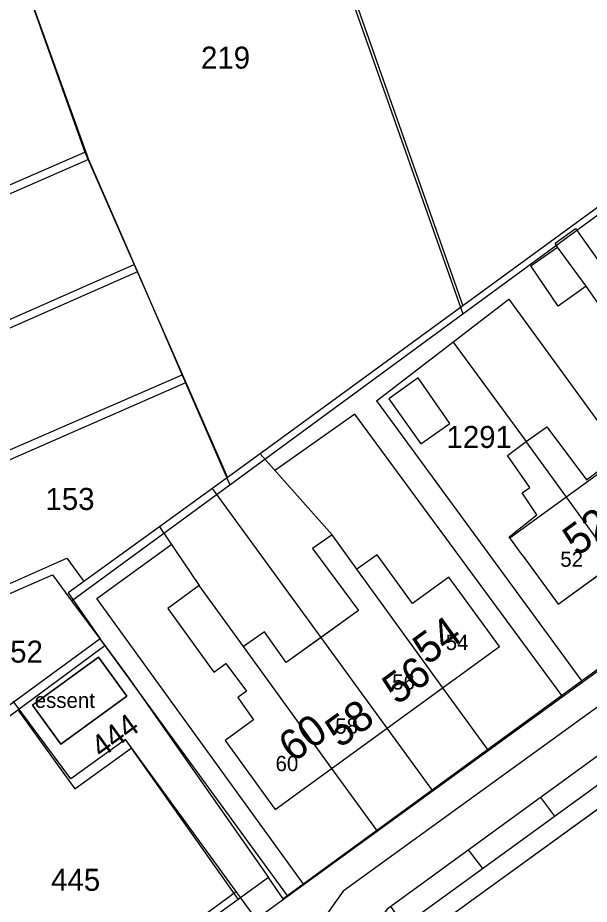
# Model space of a CAD drawing. Extents: x 148816 to 151297, y 399515 to 402500.
# Drawn here: x 149560.2 to 149607, y 400379.3 to 400451.8 of the extents above; entities that cross this region are included whole.
import ezdxf

# ---------------------------------------------------------------- set-up
doc = ezdxf.new("R2010")
doc.units = 0
for name, color, linetype in [('B01 Hoofdgebouw  [D] Norm', 7, 'Continuous'), ('B01 Hoofdgebouw  [T] Norm', 7, 'Continuous'), ('B01 hoofgebouw', 7, 'Continuous'), ('B07 Tussenmuur  [D] Norm', 7, 'Continuous'), ('G01 perceelsgrens', 7, 'Continuous'), ('T04 Haag heg  [D] Gem', 7, 'Continuous'), ('V00 Kant verharding algemeen  [T] Norm', 7, 'Continuous'), ('V00 Kant verharding algemeen secundair  [T] Gem', 7, 'Continuous'), ('Z01 perceelnummer', 7, 'Continuous'), ('Z02 huisnummer', 7, 'Continuous'), ('Z02 Huisnummer  [Tekst] Norm', 7, 'Continuous'), ('Z19 Overige Tekst  [Tekst] Gem', 7, 'Continuous')]:
    doc.layers.add(name, color=color, linetype=linetype)

msp = doc.modelspace()

# ---------------------------------------------------------------- linework, layer by layer
at = {"layer": 'B01 Hoofdgebouw  [D] Norm'}
for p, q in [((149578.674, 400400.387), (149575.05, 400405.38)), ((149580.38, 400401.594), (149578.674, 400400.387))]:
    msp.add_line(p, q, dxfattribs=at)
for points in [[(149610.97, 400423.826), (149606.716, 400429.876), (149604.419, 400428.237), (149602.204, 400431.555), (149604.374, 400433.068), (149604.198, 400433.399), (149605.857, 400434.609), (149614.619, 400422.278)], [(149606.716, 400429.876), (149604.374, 400433.068)], [(149600.411, 400409.373), (149602.683, 400411.165), (149601.475, 400412.977), (149602.113, 400413.406), (149600.275, 400416.035), (149601.807, 400417.17), (149603.491, 400418.38), (149606.741, 400414.039), (149609.549, 400416.132)], [(149595.489, 400406.057), (149592.499, 400403.905), (149589.603, 400407.888), (149587.944, 400406.729), (149585.93, 400409.537), (149584.322, 400408.403), (149588.075, 400403.347), (149585.037, 400401.129), (149582.153, 400399.087), (149580.38, 400401.594)], [(149601.48, 400407.9), (149600.411, 400409.373)], [(149596.68, 400404.42), (149595.489, 400406.057)]]:
    msp.add_lwpolyline(points, dxfattribs=at)
msp.add_lwpolyline([(149590.574, 400420.669), (149593.193, 400416.967), (149595.566, 400418.631), (149592.974, 400422.383)], close=True, dxfattribs=at)
at = {"layer": 'B01 Hoofdgebouw  [T] Norm'}
for p, q in [((149604.42, 400403.85), (149632.08, 400423.92)), ((149601.48, 400407.9), (149604.42, 400403.85)), ((149575.05, 400405.38), (149572.46, 400403.5)), ((149599.62, 400400.38), (149596.68, 400404.42)), ((149572.46, 400403.5), (149576.25, 400398.3)), ((149581.26, 400387.05), (149599.62, 400400.38)), ((149566.8, 400399.51), (149561.39, 400395.6)), ((149569.11, 400396.32), (149566.8, 400399.51)), ((149576.25, 400398.3), (149577.21, 400399.01)), ((149577.21, 400399.01), (149578.9, 400396.73)), ((149578.9, 400396.73), (149578.19, 400396.22)), ((149563.7, 400392.41), (149569.11, 400396.32)), ((149578.19, 400396.22), (149579.48, 400394.39)), ((149561.39, 400395.6), (149563.7, 400392.41)), ((149579.48, 400394.39), (149577.16, 400392.7)), ((149577.16, 400392.7), (149581.26, 400387.05))]:
    msp.add_line(p, q, dxfattribs=at)
at = {"layer": 'B01 hoofgebouw'}
for points in [[(149601.48, 400407.9), (149600.475, 400409.284), (149628.135, 400429.354), (149629.14, 400427.97)], [(149601.48, 400407.9), (149604.42, 400403.85), (149632.08, 400423.92), (149629.14, 400427.97)], [(149596.68, 400404.42), (149595.489, 400406.057), (149592.499, 400403.905), (149589.603, 400407.888), (149587.944, 400406.729), (149585.93, 400409.537), (149584.322, 400408.403), (149588.075, 400403.347), (149582.153, 400399.087), (149580.38, 400401.594), (149578.674, 400400.387), (149575.05, 400405.38)], [(149575.05, 400405.38), (149572.46, 400403.5), (149576.25, 400398.3), (149577.21, 400399.01), (149578.9, 400396.73), (149578.19, 400396.22), (149579.48, 400394.39), (149577.16, 400392.7), (149581.26, 400387.05), (149599.62, 400400.38), (149596.68, 400404.42)], [(149566.8, 400399.51), (149569.11, 400396.32), (149563.7, 400392.41), (149561.39, 400395.6), (149566.8, 400399.51)]]:
    msp.add_lwpolyline(points, dxfattribs=at)
at = {"layer": 'B07 Tussenmuur  [D] Norm'}
for p, q in [((149609.04, 400407.202), (149601.807, 400417.17)), ((149609.04, 400407.202), (149601.807, 400417.17)), ((149594.993, 400397.02), (149587.944, 400406.729)), ((149594.993, 400397.02), (149587.944, 400406.729)), ((149590.427, 400393.705), (149585.037, 400401.129)), ((149590.427, 400393.705), (149585.037, 400401.129)), ((149585.907, 400390.424), (149578.674, 400400.387)), ((149585.907, 400390.424), (149578.674, 400400.387))]:
    msp.add_line(p, q, dxfattribs=at)
at = {"layer": 'G01 perceelsgrens'}
for points in [[(149575.934, 400486.311), (149586.263, 400456.978), (149596.625, 400427.624)], [(149552.339, 400477.996), (149565.983, 400440.231)], [(149596.625, 400427.624), (149607.367, 400435.504), (149617.476, 400442.841)], [(149565.983, 400440.231), (149552.846, 400434.522)], [(149565.983, 400440.231), (149569.974, 400431.04)], [(149569.974, 400431.04), (149546.568, 400420.73), (149523.662, 400410.757)], [(149569.974, 400431.04), (149573.916, 400421.964)], [(149577.538, 400413.624), (149596.625, 400427.624)], [(149573.916, 400421.964), (149548.666, 400410.933), (149527.649, 400401.679)], [(149573.916, 400421.964), (149577.538, 400413.624)], [(149638.811, 400421.22), (149581.911, 400379.736)], [(149564.597, 400404.132), (149577.538, 400413.624)], [(149531.643, 400392.538), (149563.017, 400406.267), (149564.597, 400404.132)], [(149564.597, 400404.132), (149567.311, 400400.463)], [(149560.181, 400395.212), (149567.311, 400400.463)], [(149567.311, 400400.463), (149569.156, 400397.97), (149580.706, 400381.478)], [(149535.981, 400383.574), (149556.14, 400392.236), (149560.181, 400395.212)], [(149560.181, 400395.212), (149564.853, 400388.754), (149569.465, 400392.087), (149578.24, 400379.689)], [(149586.38, 400371.686), (149611.981, 400390.23)], [(149580.706, 400381.478), (149578.24, 400379.689)], [(149581.911, 400379.736), (149580.706, 400381.478)], [(149578.24, 400379.689), (149562.734, 400368.438), (149552.589, 400360.963)]]:
    msp.add_lwpolyline(points, dxfattribs=at)
at = {"layer": 'T04 Haag heg  [D] Gem'}
for p, q in [((149575.933, 400487.073), (149596.613, 400428.273)), ((149552.238, 400478.748), (149565.665, 400440.852)), ((149617.573, 400443.572), (149596.619, 400428.278)), ((149519.457, 400420.627), (149565.665, 400440.852)), ((149565.665, 400440.852), (149577.368, 400414.21)), ((149534.673, 400416.243), (149569.712, 400431.639)), ((149589.544, 400420.491), (149600.398, 400428.824)), ((149600.398, 400428.824), (149609.555, 400416.224)), ((149596.619, 400428.278), (149580.044, 400416.145)), ((149595.844, 400425.308), (149601.807, 400417.17)), ((149554.33, 400414.227), (149573.65, 400422.617)), ((149585.037, 400401.129), (149576.121, 400413.316)), ((149598.738, 400391.884), (149594.993, 400397.02)), ((149594.171, 400388.571), (149590.427, 400393.705)), ((149589.649, 400385.291), (149585.907, 400390.424)), ((149578.067, 400380.323), (149552.152, 400361.429))]:
    msp.add_line(p, q, dxfattribs=at)
for points in [[(149585.93, 400409.537), (149580.044, 400416.145), (149571.794, 400410.181), (149575.05, 400405.38)], [(149550.41, 400401.506), (149564.191, 400407.617), (149565.543, 400405.796)], [(149566.931, 400401.032), (149555.17, 400392.43)], [(149568.992, 400392.77), (149564.538, 400389.558), (149559.819, 400395.933)]]:
    msp.add_lwpolyline(points, dxfattribs=at)
at = {"layer": 'V00 Kant verharding algemeen  [T] Norm'}
for p, q in [((149561.383, 400353.578), (149673.64, 400434.89)), ((149589.544, 400420.491), (149606.355, 400397.558)), ((149582.296, 400379.957), (149566.931, 400401.032)), ((149579.803, 400377.942), (149568.992, 400392.77))]:
    msp.add_line(p, q, dxfattribs=at)
for points in [[(149683.03, 400453.46), (149660.686, 400437.378), (149660.952, 400437.012), (149579.946, 400378.253), (149580.045, 400378.116), (149555.602, 400360.572)], [(149689.364, 400453.335), (149637.091, 400415.374), (149636.834, 400415.188), (149633.16, 400413.903), (149586.836, 400380.371), (149584.735, 400377.431), (149557.956, 400358.172)], [(149692.632, 400451.684), (149637.083, 400411.392), (149633.449, 400410.175), (149590.434, 400378.907), (149588.204, 400375.854), (149560.275, 400355.791)], [(149604.731, 400396.374), (149587.771, 400419.394), (149581.216, 400414.78)], [(149571.794, 400410.181), (149564.303, 400404.777), (149566.931, 400401.032)], [(149583.618, 400380.917), (149566.665, 400404.328), (149572.713, 400408.713)]]:
    msp.add_lwpolyline(points, dxfattribs=at)
at = {"layer": 'V00 Kant verharding algemeen secundair  [T] Gem'}
for p, q in [((149604.166, 400386.506), (149603.002, 400388.042)), ((149598.256, 400382.219), (149597.095, 400383.749))]:
    msp.add_line(p, q, dxfattribs=at)
msp.add_lwpolyline([(149608.891, 400392.358), (149610.077, 400390.794), (149591.852, 400377.573), (149590.72, 400379.107)], dxfattribs=at)

# ---------------------------------------------------------------- texts
at = {"layer": 'Z01 perceelnummer'}
for s, p in [('219', (149575.188, 400447.68)), ('1291', (149595.287, 400416.639)), ('153', (149562.453, 400411.566)), ('152', (149558.224, 400399.075)), ('445', (149562.916, 400380.403))]:
    msp.add_text(s, height=1.8, dxfattribs=at).set_placement(p)
msp.add_text('444', height=1.8, rotation=36.09537, dxfattribs=at).set_placement((149567.025, 400391.201))
at = {"layer": 'Z02 huisnummer'}
for s, rotation, p in [('52', 35.96416, (149605.991, 400407.708)), ('54', 36.01053, (149593.719, 400398.815)), ('56', 36.01053, (149591.221, 400395.554)), ('58', 36.01053, (149586.552, 400392.02)), ('60', 36.01053, (149582.729, 400390.836))]:
    msp.add_text(s, height=2.5, rotation=rotation, dxfattribs=at).set_placement(p)
at = {"layer": 'Z02 Huisnummer  [Tekst] Norm'}
for s, p in [('52', (149604.606, 400406.916)), ('54', (149595.223, 400400.105)), ('56', (149590.841, 400396.87)), ('58', (149586.177, 400393.259)), ('60', (149581.29, 400390.196))]:
    msp.add_text(s, height=1.25, dxfattribs=at).set_placement(p)
at = {"layer": 'Z19 Overige Tekst  [Tekst] Gem'}
msp.add_text('essent', height=1.25, dxfattribs=at).set_placement((149561.574, 400395.371))

doc.saveas('drawing.dxf')
